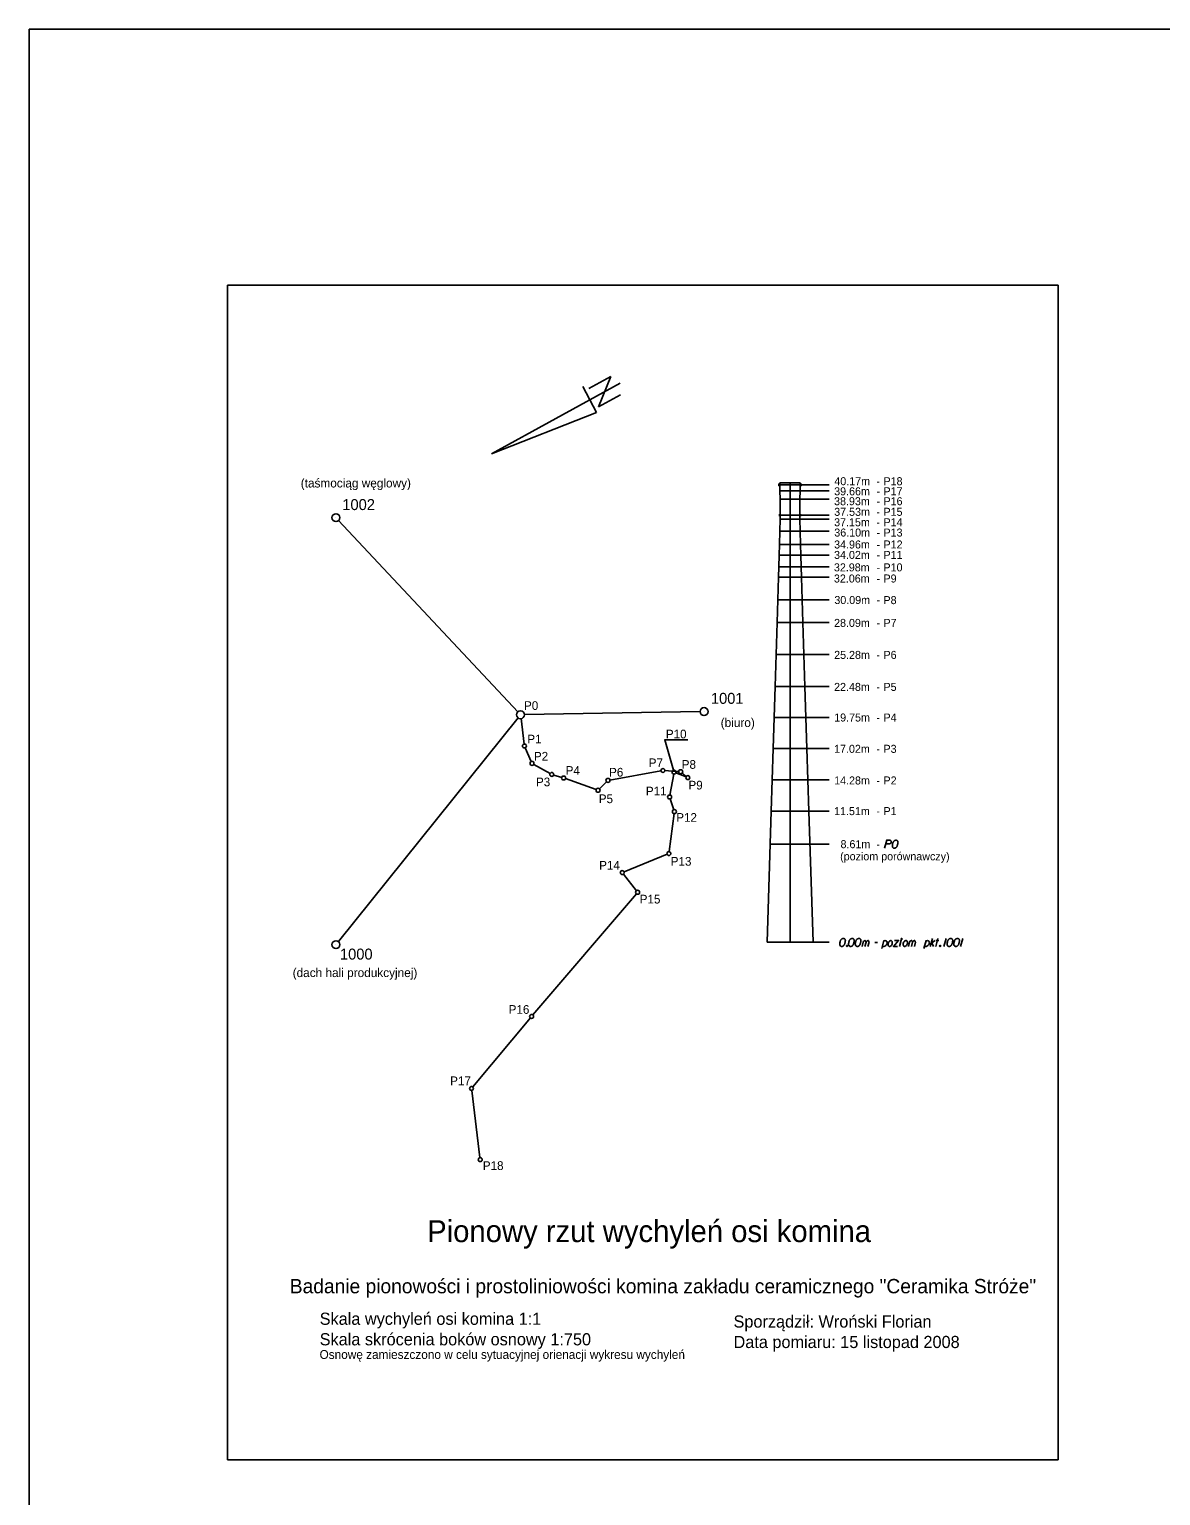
# Model space of a CAD drawing. Extents: x 138 to 6653, y -177 to 1520.
# Drawn here: x 287.42 to 316.02, y 1.58 to 38.66 of the extents above; entities that cross this region are included whole.
import ezdxf

# ---------------------------------------------------------------- set-up
doc = ezdxf.new("R2010")
doc.units = 0
for name, color, linetype in [('15 listopad 2008', 7, 'Continuous'), ('Opisy', 7, 'Continuous'), ('Ramka do drukowania', 7, 'Continuous'), ('Standart wykresów', 7, 'Continuous'), ('Wykresy 15 listopad 2008', 7, 'Continuous'), ('Wykresy 4 maj 2008', 7, 'Continuous')]:
    doc.layers.add(name, color=color, linetype=linetype)

msp = doc.modelspace()

# ---------------------------------------------------------------- linework, layer by layer
at = {"layer": '15 listopad 2008'}
msp.add_lwpolyline([(287.418, 38.661), (413.872, 38.661), (413.872, -75.347), (287.418, -75.347)], close=True, dxfattribs=at)
msp.add_lwpolyline([(303.705, 19.928), (303.485, 20.696), (304.065, 20.696)], dxfattribs=at)
at = {"layer": 'Opisy'}
for p, q in [((306.373, 27.165), (306.373, 27.141)), ((306.394, 27.165), (306.373, 27.165)), ((306.652, 27.141), (306.373, 27.141)), ((306.373, 27.141), (306.373, 27.116)), ((306.394, 27.116), (306.373, 27.116)), ((306.394, 27.19), (306.394, 27.165)), ((306.394, 27.19), (306.692, 27.19)), ((306.394, 26.993), (306.394, 27.116)), ((306.652, 15.575), (306.652, 27.19)), ((306.652, 27.141), (307.641, 27.141)), ((306.91, 27.19), (306.692, 27.19)), ((306.91, 27.19), (306.91, 27.165)), ((306.91, 27.165), (306.931, 27.165)), ((306.91, 27.116), (306.931, 27.116)), ((306.91, 26.993), (306.91, 27.116)), ((306.931, 27.165), (306.931, 27.141)), ((306.931, 27.141), (306.931, 27.116)), ((306.652, 26.993), (306.394, 26.993)), ((306.403, 26.783), (306.394, 26.993)), ((306.652, 26.783), (306.403, 26.783)), ((306.403, 26.783), (306.403, 26.405)), ((306.652, 26.993), (307.641, 26.993)), ((306.652, 26.783), (307.641, 26.783)), ((306.901, 26.783), (306.91, 26.993)), ((306.901, 26.783), (306.901, 26.405)), ((306.386, 26.405), (306.386, 26.379)), ((306.386, 26.405), (306.403, 26.405)), ((306.652, 26.379), (306.386, 26.379)), ((306.386, 26.379), (306.386, 26.354)), ((306.405, 26.354), (306.386, 26.354)), ((306.403, 26.271), (306.405, 26.354)), ((306.652, 26.379), (307.641, 26.379)), ((306.901, 26.271), (306.899, 26.354)), ((306.899, 26.354), (306.918, 26.354)), ((306.918, 26.405), (306.901, 26.405)), ((306.918, 26.405), (306.918, 26.379)), ((306.918, 26.379), (306.918, 26.354)), ((306.386, 25.638), (306.394, 25.967)), ((306.394, 25.967), (306.403, 26.271)), ((306.652, 25.967), (306.394, 25.967)), ((306.652, 26.271), (306.403, 26.271)), ((306.652, 26.271), (307.641, 26.271)), ((306.652, 25.967), (307.641, 25.967)), ((306.91, 25.967), (306.901, 26.271)), ((306.918, 25.638), (306.91, 25.967)), ((306.377, 25.368), (306.386, 25.638)), ((306.652, 25.638), (306.386, 25.638)), ((306.652, 25.638), (307.641, 25.638)), ((306.927, 25.368), (306.918, 25.638)), ((306.37, 25.069), (306.377, 25.368)), ((306.652, 25.368), (306.377, 25.368)), ((306.652, 25.368), (307.641, 25.368)), ((306.934, 25.069), (306.927, 25.368)), ((306.36, 24.804), (306.37, 25.069)), ((306.652, 25.069), (306.37, 25.069)), ((306.652, 25.069), (307.641, 25.069)), ((306.944, 24.804), (306.934, 25.069)), ((306.344, 24.236), (306.36, 24.804)), ((306.652, 24.804), (306.36, 24.804)), ((306.652, 24.804), (307.641, 24.804)), ((306.96, 24.236), (306.944, 24.804)), ((306.327, 23.662), (306.344, 24.236)), ((306.652, 24.236), (306.344, 24.236)), ((306.652, 24.236), (307.641, 24.236)), ((306.977, 23.662), (306.96, 24.236)), ((306.304, 22.851), (306.327, 23.662)), ((306.652, 23.662), (306.327, 23.662)), ((306.652, 23.662), (307.641, 23.662)), ((307, 22.851), (306.977, 23.662)), ((306.278, 22.047), (306.304, 22.851)), ((306.652, 22.851), (306.304, 22.851)), ((306.652, 22.851), (307.641, 22.851)), ((307.026, 22.047), (307, 22.851)), ((306.253, 21.261), (306.278, 22.047)), ((306.652, 22.047), (306.278, 22.047)), ((306.652, 22.047), (307.641, 22.047)), ((307.051, 21.261), (307.026, 22.047)), ((306.229, 20.476), (306.253, 21.261)), ((306.652, 21.261), (306.253, 21.261)), ((306.652, 21.261), (307.641, 21.261)), ((307.075, 20.476), (307.051, 21.261)), ((306.204, 19.685), (306.229, 20.476)), ((306.652, 20.476), (306.229, 20.476)), ((306.652, 20.476), (307.641, 20.476)), ((307.1, 19.685), (307.075, 20.476)), ((306.178, 18.889), (306.204, 19.685)), ((306.652, 19.685), (306.204, 19.685)), ((306.652, 19.685), (307.641, 19.685)), ((307.126, 18.889), (307.1, 19.685)), ((306.07, 15.575), (306.178, 18.889)), ((306.652, 18.889), (306.178, 18.889)), ((306.652, 18.889), (307.641, 18.889)), ((307.234, 15.575), (307.126, 18.889)), ((306.652, 18.053), (306.151, 18.053)), ((306.652, 18.053), (307.641, 18.053)), ((306.652, 15.575), (306.07, 15.575)), ((306.652, 15.575), (307.641, 15.575))]:
    msp.add_line(p, q, dxfattribs=at)
for points in [[(309.044, 17.955), (309.099, 18.158), (309.167, 18.158), (309.177, 18.156), (309.181, 18.155), (309.191, 18.15), (309.197, 18.145), (309.202, 18.139), (309.207, 18.131), (309.21, 18.119), (309.212, 18.11), (309.21, 18.102), (309.208, 18.096), (309.205, 18.089), (309.202, 18.084), (309.197, 18.078), (309.191, 18.073), (309.186, 18.07), (309.178, 18.067), (309.17, 18.065), (309.075, 18.065)], [(309.334, 18.158), (309.331, 18.158), (309.322, 18.156), (309.315, 18.155), (309.31, 18.153), (309.303, 18.15), (309.293, 18.145), (309.285, 18.14), (309.277, 18.134), (309.272, 18.127), (309.267, 18.119), (309.263, 18.111), (309.258, 18.102), (309.255, 18.096), (309.252, 18.086), (309.247, 18.07), (309.242, 18.046), (309.239, 18.027), (309.239, 18.009), (309.24, 17.997), (309.247, 17.982), (309.252, 17.974), (309.259, 17.965), (309.269, 17.959), (309.274, 17.957), (309.283, 17.955), (309.291, 17.955), (309.304, 17.957), (309.315, 17.96), (309.323, 17.965), (309.334, 17.973), (309.339, 17.978), (309.346, 17.984), (309.35, 17.99), (309.353, 17.995), (309.357, 18.003), (309.358, 18.006), (309.361, 18.014), (309.365, 18.024), (309.368, 18.033), (309.369, 18.04), (309.371, 18.045), (309.373, 18.051), (309.376, 18.065), (309.377, 18.073), (309.379, 18.081), (309.381, 18.092), (309.382, 18.107), (309.382, 18.111), (309.381, 18.118), (309.379, 18.124), (309.374, 18.134), (309.369, 18.14), (309.365, 18.145), (309.358, 18.15), (309.352, 18.153), (309.347, 18.155), (309.342, 18.156), (309.334, 18.158)], [(308.003, 15.673), (308, 15.673), (307.991, 15.672), (307.984, 15.67), (307.979, 15.668), (307.971, 15.665), (307.962, 15.66), (307.954, 15.656), (307.946, 15.649), (307.941, 15.643), (307.936, 15.635), (307.932, 15.627), (307.927, 15.617), (307.924, 15.611), (307.92, 15.601), (307.916, 15.586), (307.911, 15.562), (307.908, 15.543), (307.908, 15.525), (307.909, 15.512), (307.916, 15.498), (307.92, 15.49), (307.928, 15.48), (307.938, 15.474), (307.943, 15.472), (307.952, 15.471), (307.96, 15.471), (307.973, 15.472), (307.984, 15.476), (307.992, 15.48), (308.003, 15.488), (308.008, 15.493), (308.014, 15.499), (308.019, 15.506), (308.022, 15.511), (308.026, 15.519), (308.027, 15.522), (308.03, 15.53), (308.034, 15.539), (308.037, 15.549), (308.038, 15.555), (308.04, 15.56), (308.042, 15.566), (308.045, 15.581), (308.046, 15.589), (308.048, 15.597), (308.05, 15.608), (308.051, 15.622), (308.051, 15.627), (308.05, 15.633), (308.048, 15.64), (308.043, 15.649), (308.038, 15.656), (308.034, 15.66), (308.027, 15.665), (308.021, 15.668), (308.016, 15.67), (308.011, 15.672), (308.003, 15.673)], [(308.228, 15.673), (308.225, 15.673), (308.215, 15.672), (308.209, 15.67), (308.204, 15.668), (308.196, 15.665), (308.187, 15.66), (308.179, 15.656), (308.171, 15.649), (308.166, 15.643), (308.161, 15.635), (308.156, 15.627), (308.151, 15.617), (308.148, 15.611), (308.145, 15.601), (308.14, 15.586), (308.136, 15.562), (308.132, 15.543), (308.132, 15.525), (308.134, 15.512), (308.14, 15.498), (308.145, 15.49), (308.153, 15.48), (308.163, 15.474), (308.167, 15.472), (308.177, 15.471), (308.185, 15.471), (308.198, 15.472), (308.209, 15.476), (308.217, 15.48), (308.228, 15.488), (308.233, 15.493), (308.239, 15.499), (308.244, 15.506), (308.247, 15.511), (308.25, 15.519), (308.252, 15.522), (308.255, 15.53), (308.258, 15.539), (308.261, 15.549), (308.263, 15.555), (308.265, 15.56), (308.266, 15.566), (308.269, 15.581), (308.271, 15.589), (308.273, 15.597), (308.274, 15.608), (308.276, 15.622), (308.276, 15.627), (308.274, 15.633), (308.273, 15.64), (308.268, 15.649), (308.263, 15.656), (308.258, 15.66), (308.252, 15.665), (308.246, 15.668), (308.241, 15.67), (308.236, 15.672), (308.228, 15.673)], [(308.398, 15.673), (308.395, 15.673), (308.386, 15.672), (308.379, 15.67), (308.375, 15.668), (308.367, 15.665), (308.357, 15.66), (308.349, 15.656), (308.341, 15.649), (308.336, 15.643), (308.332, 15.635), (308.327, 15.627), (308.322, 15.617), (308.319, 15.611), (308.316, 15.601), (308.311, 15.586), (308.306, 15.562), (308.303, 15.543), (308.303, 15.525), (308.304, 15.512), (308.311, 15.498), (308.316, 15.49), (308.324, 15.48), (308.333, 15.474), (308.338, 15.472), (308.347, 15.471), (308.355, 15.471), (308.368, 15.472), (308.379, 15.476), (308.387, 15.48), (308.398, 15.488), (308.403, 15.493), (308.41, 15.499), (308.414, 15.506), (308.418, 15.511), (308.421, 15.519), (308.422, 15.522), (308.426, 15.53), (308.429, 15.539), (308.432, 15.549), (308.434, 15.555), (308.435, 15.56), (308.437, 15.566), (308.44, 15.581), (308.442, 15.589), (308.443, 15.597), (308.445, 15.608), (308.446, 15.622), (308.446, 15.627), (308.445, 15.633), (308.443, 15.64), (308.438, 15.649), (308.434, 15.656), (308.429, 15.66), (308.422, 15.665), (308.416, 15.668), (308.411, 15.67), (308.406, 15.672), (308.398, 15.673)], [(308.473, 15.471), (308.51, 15.616)], [(308.5, 15.578), (308.508, 15.595), (308.516, 15.605), (308.526, 15.611), (308.536, 15.616), (308.542, 15.619), (308.551, 15.619), (308.555, 15.617), (308.561, 15.611), (308.567, 15.603), (308.572, 15.589), (308.574, 15.581), (308.582, 15.595), (308.591, 15.605), (308.601, 15.611), (308.61, 15.616), (308.618, 15.619), (308.626, 15.619), (308.633, 15.617), (308.638, 15.611), (308.642, 15.603), (308.647, 15.589), (308.649, 15.581), (308.622, 15.471)], [(308.547, 15.471), (308.574, 15.581)], [(308.969, 15.418), (309.023, 15.617)], [(309.019, 15.6), (309.035, 15.613), (309.058, 15.617), (309.078, 15.614), (309.09, 15.605), (309.1, 15.592), (309.106, 15.574), (309.108, 15.558), (309.105, 15.544), (309.1, 15.527), (309.087, 15.507), (309.071, 15.49), (309.047, 15.474), (309.027, 15.471), (309.007, 15.472), (308.987, 15.484)], [(309.197, 15.617), (309.208, 15.617), (309.221, 15.611), (309.234, 15.594), (309.235, 15.586), (309.237, 15.578), (309.237, 15.571), (309.237, 15.547), (309.232, 15.531), (309.224, 15.512), (309.215, 15.496), (309.199, 15.482), (309.184, 15.471), (309.16, 15.471), (309.151, 15.474), (309.141, 15.482), (309.137, 15.49), (309.13, 15.509), (309.13, 15.538), (309.133, 15.547), (309.14, 15.568), (309.146, 15.579), (309.149, 15.586), (309.165, 15.603), (309.181, 15.613), (309.197, 15.617)], [(309.293, 15.621), (309.396, 15.621), (309.264, 15.471), (309.366, 15.471)], [(309.423, 15.471), (309.465, 15.625)], [(309.468, 15.673), (309.476, 15.673), (309.481, 15.67), (309.486, 15.664), (309.486, 15.656), (309.481, 15.649), (309.476, 15.646), (309.468, 15.646), (309.463, 15.649), (309.458, 15.656), (309.458, 15.664), (309.463, 15.67), (309.468, 15.673)], [(309.58, 15.617), (309.591, 15.617), (309.603, 15.611), (309.616, 15.594), (309.618, 15.586), (309.619, 15.578), (309.619, 15.571), (309.619, 15.547), (309.615, 15.531), (309.607, 15.512), (309.597, 15.496), (309.581, 15.482), (309.567, 15.471), (309.543, 15.471), (309.533, 15.474), (309.524, 15.482), (309.519, 15.49), (309.513, 15.509), (309.513, 15.538), (309.516, 15.547), (309.522, 15.568), (309.529, 15.579), (309.532, 15.586), (309.548, 15.603), (309.564, 15.613), (309.58, 15.617)], [(309.646, 15.471), (309.683, 15.616)], [(309.674, 15.578), (309.682, 15.595), (309.69, 15.605), (309.699, 15.611), (309.709, 15.616), (309.715, 15.619), (309.725, 15.619), (309.728, 15.617), (309.734, 15.611), (309.74, 15.603), (309.745, 15.589), (309.747, 15.581), (309.755, 15.595), (309.764, 15.605), (309.774, 15.611), (309.784, 15.616), (309.791, 15.619), (309.799, 15.619), (309.806, 15.617), (309.811, 15.611), (309.815, 15.603), (309.82, 15.589), (309.822, 15.581), (309.795, 15.471)], [(309.72, 15.471), (309.747, 15.581)], [(310.037, 15.418), (310.091, 15.617)], [(310.086, 15.6), (310.102, 15.613), (310.126, 15.617), (310.145, 15.614), (310.158, 15.605), (310.168, 15.592), (310.174, 15.574), (310.176, 15.558), (310.172, 15.544), (310.168, 15.527), (310.155, 15.507), (310.139, 15.49), (310.115, 15.474), (310.094, 15.471), (310.075, 15.472), (310.054, 15.484)], [(310.198, 15.471), (310.252, 15.673)], [(310.217, 15.543), (310.313, 15.622)], [(310.34, 15.471), (310.392, 15.673)], [(310.34, 15.617), (310.416, 15.617)], [(310.596, 15.673), (310.542, 15.471)], [(310.719, 15.673), (310.716, 15.673), (310.706, 15.672), (310.7, 15.67), (310.695, 15.668), (310.687, 15.665), (310.678, 15.66), (310.67, 15.656), (310.662, 15.649), (310.657, 15.643), (310.652, 15.635), (310.647, 15.627), (310.642, 15.617), (310.639, 15.611), (310.636, 15.601), (310.631, 15.586), (310.627, 15.562), (310.623, 15.543), (310.623, 15.525), (310.625, 15.512), (310.631, 15.498), (310.636, 15.49), (310.644, 15.48), (310.654, 15.474), (310.658, 15.472), (310.668, 15.471), (310.676, 15.471), (310.689, 15.472), (310.7, 15.476), (310.708, 15.48), (310.719, 15.488), (310.724, 15.493), (310.73, 15.499), (310.735, 15.506), (310.738, 15.511), (310.741, 15.519), (310.743, 15.522), (310.746, 15.53), (310.749, 15.539), (310.752, 15.549), (310.754, 15.555), (310.756, 15.56), (310.757, 15.566), (310.76, 15.581), (310.762, 15.589), (310.764, 15.597), (310.765, 15.608), (310.767, 15.622), (310.767, 15.627), (310.765, 15.633), (310.764, 15.64), (310.759, 15.649), (310.754, 15.656), (310.749, 15.66), (310.743, 15.665), (310.736, 15.668), (310.732, 15.67), (310.727, 15.672), (310.719, 15.673)], [(310.889, 15.673), (310.886, 15.673), (310.877, 15.672), (310.87, 15.67), (310.866, 15.668), (310.858, 15.665), (310.848, 15.66), (310.84, 15.656), (310.832, 15.649), (310.827, 15.643), (310.823, 15.635), (310.818, 15.627), (310.813, 15.617), (310.81, 15.611), (310.807, 15.601), (310.802, 15.586), (310.797, 15.562), (310.794, 15.543), (310.794, 15.525), (310.795, 15.512), (310.802, 15.498), (310.807, 15.49), (310.815, 15.48), (310.824, 15.474), (310.829, 15.472), (310.838, 15.471), (310.846, 15.471), (310.859, 15.472), (310.87, 15.476), (310.878, 15.48), (310.889, 15.488), (310.894, 15.493), (310.901, 15.499), (310.905, 15.506), (310.909, 15.511), (310.912, 15.519), (310.913, 15.522), (310.917, 15.53), (310.92, 15.539), (310.923, 15.549), (310.925, 15.555), (310.926, 15.56), (310.928, 15.566), (310.931, 15.581), (310.932, 15.589), (310.934, 15.597), (310.936, 15.608), (310.937, 15.622), (310.937, 15.627), (310.936, 15.633), (310.934, 15.64), (310.929, 15.649), (310.925, 15.656), (310.92, 15.66), (310.913, 15.665), (310.907, 15.668), (310.902, 15.67), (310.897, 15.672), (310.889, 15.673)], [(311.019, 15.673), (310.964, 15.471)], [(308.088, 15.498), (308.096, 15.498), (308.1, 15.495), (308.105, 15.488), (308.105, 15.48), (308.1, 15.474), (308.096, 15.471), (308.088, 15.471), (308.083, 15.474), (308.078, 15.48), (308.078, 15.488), (308.083, 15.495), (308.088, 15.498)], [(308.792, 15.573), (308.861, 15.573)], [(310.236, 15.558), (310.278, 15.471)], [(310.443, 15.498), (310.451, 15.498), (310.456, 15.495), (310.461, 15.488), (310.461, 15.48), (310.456, 15.474), (310.451, 15.471), (310.443, 15.471), (310.438, 15.474), (310.434, 15.48), (310.434, 15.488), (310.438, 15.495), (310.443, 15.498)]]:
    msp.add_lwpolyline(points, dxfattribs=at)
at = {"layer": 'Ramka do drukowania'}
for p, q in [((292.431, 2.492), (292.431, 32.192)), ((292.431, 32.192), (313.431, 32.192)), ((313.431, 2.492), (313.431, 32.192)), ((292.431, 2.492), (313.431, 2.492))]:
    msp.add_line(p, q, dxfattribs=at)
at = {"layer": 'Standart wykresów'}
for p, q in [((302.36, 29.711), (299.104, 27.93)), ((302.121, 29.879), (301.564, 29.582)), ((301.81, 29.119), (302.121, 29.879)), ((301.759, 28.974), (301.412, 29.632)), ((302.367, 29.415), (301.81, 29.119)), ((299.104, 27.93), (301.759, 28.974)), ((295.171, 26.313), (295.171, 26.313)), ((299.77, 21.402), (295.239, 26.24)), ((299.776, 21.251), (295.234, 15.593)), ((299.938, 21.331), (304.378, 21.407)), ((304.478, 21.408), (304.478, 21.408)), ((295.171, 15.515), (295.171, 15.515))]:
    msp.add_line(p, q, dxfattribs=at)
for centre in [(295.171, 26.313), (304.478, 21.408), (295.171, 15.515)]:
    msp.add_circle(centre, 0.1, dxfattribs=at)
at = {"layer": 'Wykresy 15 listopad 2008'}
for p, q in [((299.932, 20.589), (299.851, 21.23)), ((299.958, 20.494), (300.109, 20.145)), ((300.172, 20.075), (300.585, 19.844)), ((300.676, 19.805), (300.881, 19.744)), ((300.976, 19.713), (301.751, 19.436)), ((302.098, 19.678), (303.389, 19.911)), ((303.488, 19.916), (303.675, 19.904)), ((303.71, 19.83), (303.617, 19.299)), ((303.675, 19.904), (303.765, 19.898)), ((303.765, 19.898), (303.839, 19.893)), ((304.022, 19.758), (303.765, 19.861)), ((303.927, 19.857), (304.03, 19.771)), ((301.834, 19.455), (302.013, 19.634)), ((303.624, 19.202), (303.713, 18.927)), ((303.722, 18.83), (303.595, 17.869)), ((303.542, 17.801), (302.455, 17.358)), ((302.439, 17.3), (302.768, 16.879)), ((302.766, 16.801), (300.151, 13.737)), ((300.086, 13.661), (298.63, 11.918)), ((298.604, 11.83), (298.812, 10.129))]:
    msp.add_line(p, q, dxfattribs=at)
for centre, radius in [((299.838, 21.329), 0.1), ((299.938, 20.539), 0.05), ((300.128, 20.099), 0.05), ((300.628, 19.819), 0.05), ((300.928, 19.729), 0.05), ((302.048, 19.669), 0.05), ((303.438, 19.919), 0.05), ((303.718, 19.879), 0.05), ((303.888, 19.889), 0.05), ((304.068, 19.739), 0.05), ((301.798, 19.419), 0.05), ((303.608, 19.249), 0.05), ((303.728, 18.879), 0.05), ((303.588, 17.819), 0.05), ((302.408, 17.339), 0.05), ((302.798, 16.839), 0.05), ((300.118, 13.699), 0.05), ((298.598, 11.879), 0.05), ((298.818, 10.079), 0.05)]:
    msp.add_circle(centre, radius, dxfattribs=at)
at = {"layer": 'Wykresy 4 maj 2008'}
msp.add_circle((299.838, 21.329), 0.1, dxfattribs=at)

# ---------------------------------------------------------------- texts
at = {"layer": 'Opisy'}
for s, height, p in [('40.17m', 0.2024, (307.772, 27.133)), ('39.66m', 0.2024, (307.768, 26.878)), ('-', 0.202, (308.835, 27.133)), ('P18', 0.2024, (309.015, 27.133)), ('P17', 0.2024, (309.015, 26.878)), ('38.93m', 0.2024, (307.766, 26.627)), ('-', 0.202, (308.837, 26.878)), ('-', 0.202, (308.841, 26.627)), ('P16', 0.2024, (309.015, 26.627)), ('37.53m', 0.2024, (307.769, 26.359)), ('-', 0.202, (308.835, 26.359)), ('P15', 0.2024, (309.015, 26.359)), ('37.15m', 0.2024, (307.767, 26.095)), ('36.10m', 0.2024, (307.771, 25.835)), ('-', 0.202, (308.835, 26.095)), ('P14', 0.2024, (309.015, 26.095)), ('P13', 0.2024, (309.015, 25.835)), ('34.96m', 0.2024, (307.767, 25.533)), ('-', 0.202, (308.837, 25.835)), ('-', 0.202, (308.837, 25.533)), ('P12', 0.2024, (309.016, 25.533)), ('34.02m', 0.2024, (307.766, 25.269)), ('-', 0.202, (308.837, 25.269)), ('P11', 0.2024, (309.015, 25.269)), ('32.98m', 0.2024, (307.762, 24.954)), ('32.06m', 0.2024, (307.762, 24.673)), ('-', 0.202, (308.837, 24.954)), ('P10', 0.2024, (309.015, 24.954)), ('P9', 0.2024, (309.015, 24.673)), ('-', 0.202, (308.837, 24.673)), ('30.09m', 0.2024, (307.773, 24.129)), ('-', 0.202, (308.837, 24.129)), ('P8', 0.2024, (309.015, 24.126)), ('28.09m', 0.2024, (307.766, 23.55)), ('P7', 0.2024, (309.015, 23.55)), ('-', 0.202, (308.837, 23.55)), ('25.28m', 0.2024, (307.768, 22.741)), ('-', 0.202, (308.835, 22.741)), ('P6', 0.2024, (309.015, 22.741)), ('22.48m', 0.2024, (307.766, 21.932)), ('-', 0.202, (308.835, 21.932)), ('P5', 0.2024, (309.015, 21.932)), ('19.75m', 0.2024, (307.769, 21.158)), ('-', 0.202, (308.835, 21.158)), ('P4', 0.2024, (309.015, 21.158)), ('17.02m', 0.2024, (307.766, 20.366)), ('-', 0.202, (308.835, 20.366)), ('P3', 0.2024, (309.015, 20.366)), ('14.28m', 0.2024, (307.768, 19.566)), ('-', 0.202, (308.836, 19.566)), ('P2', 0.2024, (309.015, 19.566)), ('11.51m', 0.2024, (307.766, 18.791)), ('P1', 0.2024, (309.016, 18.791)), ('-', 0.202, (308.835, 18.791)), ('(poziom porównawczy)', 0.2024, (307.919, 17.648)), ('8.61m', 0.2024, (307.929, 17.955)), ('-', 0.202, (308.835, 17.955)), ('Pionowy rzut wychyleń osi komina', 0.55314, (297.477, 7.994)), ('Badanie pionowości i prostoliniowości komina zakładu ceramicznego "Ceramika Stróże"', 0.36281, (294.004, 6.699)), ('Skala wychyleń osi komina 1:1', 0.30766, (294.76, 5.902)), ('Sporządził: Wroński Florian', 0.30766, (305.223, 5.832)), ('Skala skrócenia boków osnowy 1:750', 0.30766, (294.76, 5.383)), ('Data pomiaru: 15 listopad 2008', 0.30766, (305.223, 5.315)), ('Osnowę zamieszczono w celu sytuacyjnej orienacji wykresu wychyleń', 0.22315, (294.757, 5.04))]:
    msp.add_text(s, height=height, dxfattribs=at).set_placement(p)
at = {"layer": 'Standart wykresów'}
for s, height, p in [('(taśmociąg węglowy)', 0.22315, (294.281, 27.076)), ('1002', 0.2771, (295.332, 26.505)), ('1001', 0.2771, (304.652, 21.605)), ('(biuro)', 0.2231, (304.899, 21.019)), ('1000', 0.2771, (295.273, 15.138)), ('(dach hali produkcyjnej)', 0.22315, (294.077, 14.696))]:
    msp.add_text(s, height=height, dxfattribs=at).set_placement(p)
at = {"layer": 'Wykresy 4 maj 2008'}
for s, p in [('P0', (299.927, 21.451)), ('P1', (300.009, 20.604)), ('P10', (303.512, 20.731)), ('P2', (300.176, 20.169)), ('P4', (300.979, 19.81)), ('P7', (303.08, 20.004)), ('P8', (303.914, 19.962)), ('P3', (300.229, 19.52)), ('P6', (302.077, 19.766)), ('P9', (304.084, 19.439)), ('P5', (301.817, 19.094)), ('P11', (303.007, 19.289)), ('P12', (303.775, 18.622)), ('P14', (301.826, 17.413)), ('P13', (303.636, 17.512)), ('P15', (302.852, 16.556)), ('P16', (299.538, 13.766)), ('P17', (298.059, 11.962)), ('P18', (298.885, 9.818))]:
    msp.add_text(s, height=0.22, dxfattribs=at).set_placement(p)

doc.saveas('drawing.dxf')
